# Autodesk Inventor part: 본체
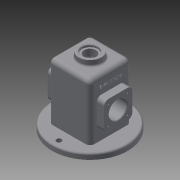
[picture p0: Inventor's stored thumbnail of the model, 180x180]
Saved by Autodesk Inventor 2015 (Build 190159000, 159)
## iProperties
Created: 2021-08
Part Number: 본체
Material: 일반
Document SubType Name: Modeling
Designer: 1048888
Density: 1 g/cm^3
Appearance: 기본값
Author: 1048888
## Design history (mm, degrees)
sketch "스케치1"
  geometry: L1 (-37, -37)-(37, -37); L2 (37, -37)-(37, 37); L3 (37, 37)-(-37, 37); L4 (-37, 37)-(-37, -37); L5 (-37, -37)-(37, 37); L6 (37, -37)-(-37, 37); 1 further point
  constraints: 12 end point, 2 midpoint, 2 parallel, 1 horizontal, 1 perpendicular
  dimensions: "d0" = 74 distance of L1.end L2.end; "d1" = 74 distance of L1.start L1.end
extrude "돌출1" new body sketch "스케치1" distance "d2" = 110; taper "d3" = 0 deg
feature "쉘1" dims "d4" = 5
sketch "스케치2"
  geometry: L1 (37, -37)-(-37, -37) reference; L2 (37, 37)-(37, -37) reference; L3 (-37, 37)-(37, 37) reference; L4 (-37, -37)-(-37, 37) reference; C1 r 67 at (0, 0); 1 further point
  constraints: 1 centre point, 1 coincident
  dimensions: "d5" = 134 diameter of C1
extrude "돌출2" join sketch "스케치2" distance "d6" = 10; taper "d7" = 0 deg
sketch "스케치3"
  geometry: L1 (100, 0)-(0, 0) reference; L2 (80, 62)-(30, 62); L3 (30, 62)-(30, 12); L4 (30, 12)-(80, 12); L5 (80, 12)-(80, 62); L6 (80, 62)-(30, 12); L7 (30, 62)-(80, 12); L8 (110, 104)-(110, -30) reference; 2 further points
  constraints: 12 end point, 2 midpoint, 2 parallel, 1 horizontal, 1 perpendicular
  dimensions: "d8" = 55 distance from line of L8 point (55, 37); "d9" = 50 distance of L2.start L2.end; "d10" = 50 distance of L2.end L3.end; "d11" = 12 distance between parallel lines of L1 L4
extrude "돌출3" join sketch "스케치3" distance "d12" = 87; taper "d14" = 0 deg; dims "d13" = 13, "d15" = 0
sketch "스케치4"
  geometry: L1 (30, 12)-(80, 62); C1 r 16 at (55, 37); 1 further point
  constraints: 2 end point, 1 centre point, 1 midpoint
  dimensions: "d16" = 32 diameter of C1
extrude "돌출4" cut sketch "스케치4" stored distance "d17" = 87; taper "d18" = 0 deg
sketch "스케치5"
  geometry: C1 r 20 at (0, 0); 1 further point
  constraints: 1 centre point, 1 coincident
  dimensions: "d19" = 40 diameter of C1
extrude "돌출5" join sketch "스케치5" distance "d20" = 10; taper "d21" = 0 deg
sketch "스케치6"
  geometry: C1 r 20 at (0, 0) reference
hole "구멍1" sketch "스케치6" at (0, 0) diameter "d22" = 21; stored, may be unused: countersink angle "d26" = 90 deg, drill point angle "d28" = 118 deg; dims "d23" = 6, "d24" = 28, "d25" = 4, "d27" = 8
fillet "모깎기1" dims "d29" = 8
fillet "모깎기2" dims "d30" = 8
sketch "스케치7"
  geometry: A1 r 8 centre (72, 54) between (80, 54) and (72, 62) reference; A2 r 8 centre (38, 54) between (38, 62) and (30, 54) reference; A3 r 8 centre (38, 20) between (30, 20) and (38, 12) reference; A4 r 8 centre (72, 20) between (72, 12) and (80, 20) reference; 1 further point
hole "구멍2" sketch "스케치7" diameter "d31" = 3.242; stored, may be unused: countersink angle "d35" = 90 deg, drill point angle "d37" = 118 deg; dims "d32" = 8, "d33" = 4, "d34" = 2, "d36" = 10
sketch "스케치9"
  geometry: C1 r 67 at (0, 0) reference; 1 further point
  constraints: 1 vertical alignment
  dimensions: "d38" = 55 distance of C1.centre point (0, 55)
hole "구멍3" sketch "스케치9" at (0, 55) diameter "d39" = 9; stored, may be unused: countersink angle "d43" = 90 deg, drill point angle "d45" = 118 deg; dims "d40" = 8, "d41" = 4, "d42" = 2, "d44" = 10
fillet "모깎기3" dims "d46" = 8
sketch "스케치10"
  geometry: L1 (-25, 25)-(25, 25); L2 (25, 25)-(25, -25); L3 (25, -25)-(-25, -25); L4 (-25, -25)-(-25, 25); L5 (-25, 25)-(25, -25); L6 (25, 25)-(-25, -25); C1 r 67 at (0, 0) reference
  constraints: 12 end point, 2 midpoint, 2 parallel, 1 horizontal, 1 perpendicular
  dimensions: "d47" = 50 distance of L2.end L3.end; "d48" = 50 distance of L1.end L2.end
extrude "돌출6" cut sketch "스케치10" distance "d49" = 100; taper "d50" = 0 deg
feature "면 기울기1" dims angle "d51" = 20 deg
feature "면 기울기2" dims angle "d52" = 20 deg
fillet "모깎기4" dims "d53" = 8
fillet "모깎기5" dims "d54" = 3
fillet "모깎기6" dims "d55" = 3
fillet "모깎기7" dims "d56" = 3
chamfer "모따기1" distance "d57" = 1; stored, may be unused: second distance "d58" = 2, angle "d59" = 45 deg
sketch "스케치11"
  geometry: L1 (-92, -8)-(0, -8) reference; L2 (-110, 49)-(-110, 9) reference; 2 further points
  constraints: 1 other
  dimensions: "d60" = 37 distance from line of L1 point (-82, 29); "d61" = 28 distance from line of point (-82, 29) L2
feature "엠보싱1" sketch "스케치11" dims "d0" = 74, "d1" = 74, "d62" = 0.5, "d63" = 0
fillet "모깎기8" dims "d64" = 3
node "솔리드1"
mirror "대칭1"
mirror "대칭2"
